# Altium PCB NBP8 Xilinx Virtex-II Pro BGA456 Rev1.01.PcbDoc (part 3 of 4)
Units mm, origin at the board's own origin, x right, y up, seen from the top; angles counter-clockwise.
Board outline 69 x 99.5 mm, 8 copper layers (Top Layer, InternalPlane1, InternalPlane2, MidLayer1, MidLayer2, MidLayer3, MidLayer4, Bottom Layer), stack 1.545 mm thick; 164 components, 314 nets, 1132 pads, 807 vias.
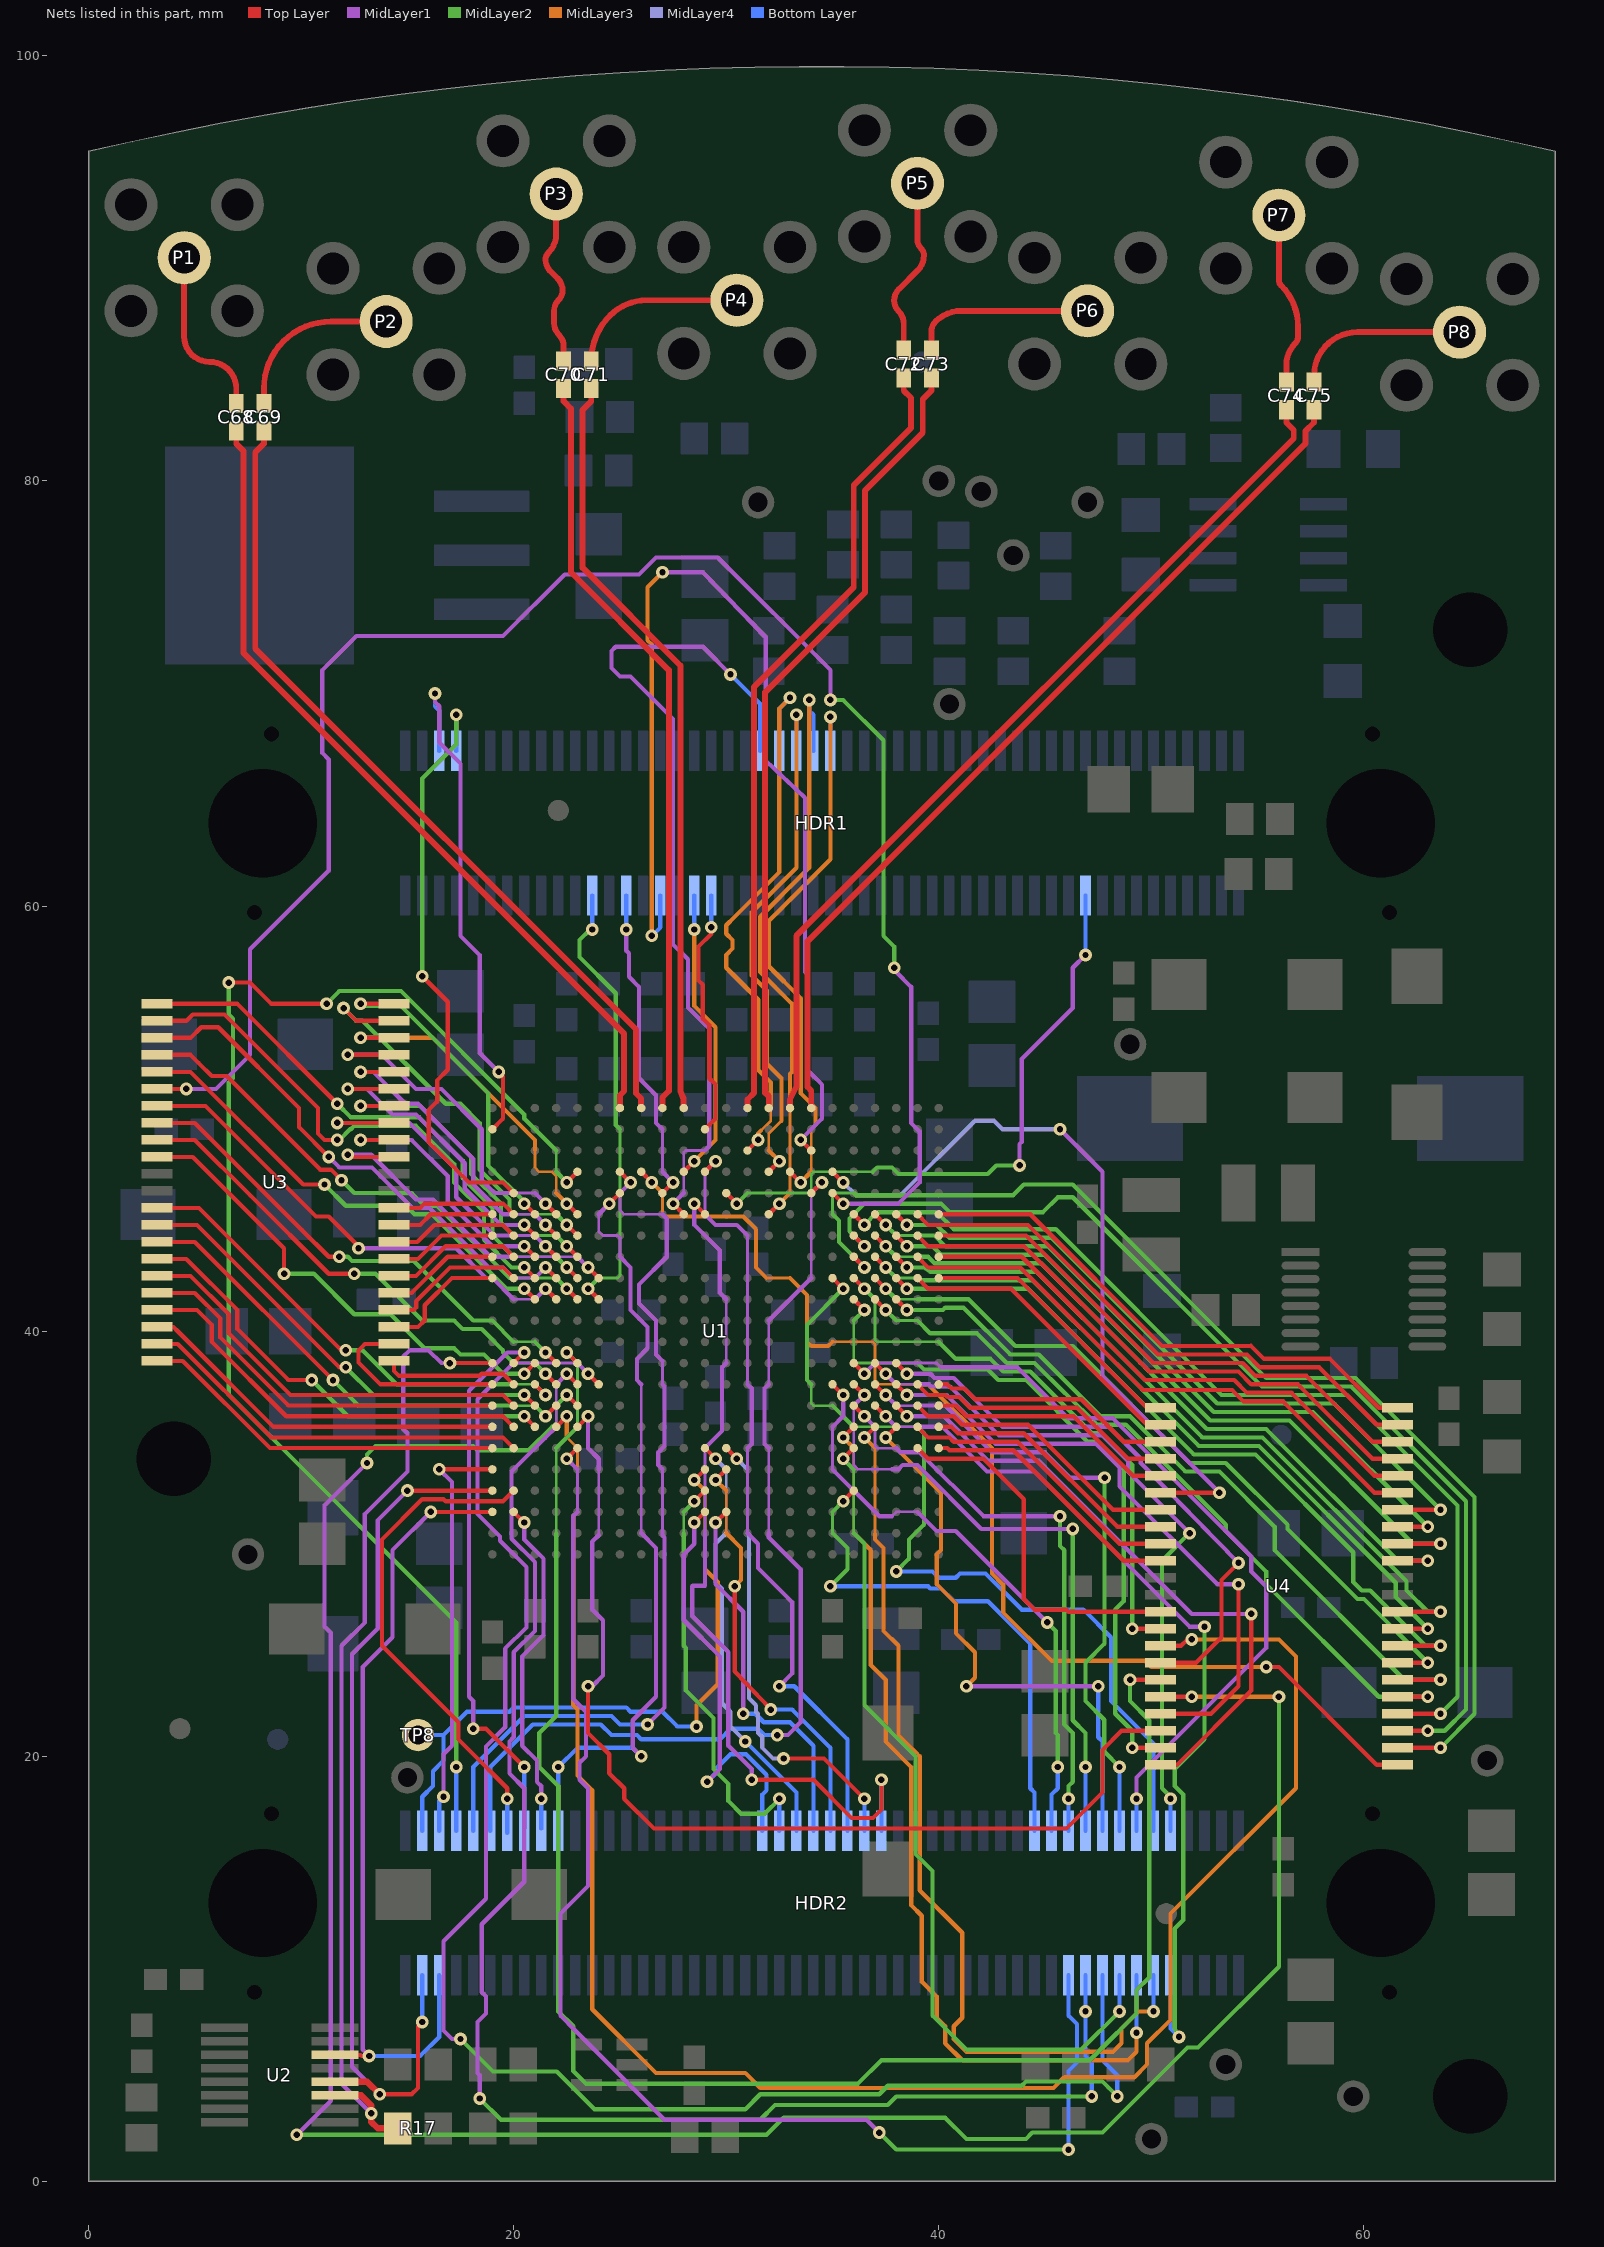
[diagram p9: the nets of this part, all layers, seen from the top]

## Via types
v1: diameter 0.6, hole 0.3, Top Layer to Bottom Layer, tented bottom, 695 vias
v2: diameter 0.9, hole 0.5, Top Layer to Bottom Layer, tented bottom, 45 vias
v3: diameter 1.8, hole 1, Top Layer to Bottom Layer, tented bottom, 26 vias
v4: diameter 1, hole 0.7, Top Layer to Bottom Layer, tented bottom, 17 vias
v5: diameter 1, hole 0.5, Top Layer to Bottom Layer, tented bottom, 15 vias
v6: diameter 1.5, hole 1, Top Layer to Bottom Layer, tented bottom, 4 vias
v7: diameter 0.8, hole 0.4, Top Layer to Bottom Layer, tented bottom, 3 vias
v8: diameter 0.9, hole 0.5, Top Layer to Bottom Layer, 2 vias

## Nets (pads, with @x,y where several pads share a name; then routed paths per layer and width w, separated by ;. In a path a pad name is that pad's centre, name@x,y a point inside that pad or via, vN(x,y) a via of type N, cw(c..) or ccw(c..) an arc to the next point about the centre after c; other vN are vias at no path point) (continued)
RAM_ADDR13: HDR1.35 U1.W13 | length 14
  Top Layer w0.2: U1.W13@28,47.5 v1(28.5,48)
  MidLayer3 w0.2: v1(28.5,48) 29.5,49 29.5,54.3 28.5,55.3 v1(28.5,58.9)
  Bottom Layer w0.2: v1(28.5,58.9) 28.5,59.1 HDR1.35@28.5,60.5
RAM_ADDR14: HDR1.31 U1.Y7 | length 51.6
  Top Layer w0.2: v1(33.5,49) U1.Y7@34,48.5
  MidLayer1 w0.2: v1(27,75.7) 28.9,75.7 31.855,72.645 31.855,66.845 33.7,65.1 33.7,56.9 33.8,56.8 33.8,52.3 34.5,51.6 34.5,50 v1(33.5,49)
  MidLayer3 w0.2: v1(26.5,58.6) 26.5,72.3 26.3,72.5 26.3,75 26.8,75.5 v1(27,75.7)
  Bottom Layer w0.2: v1(26.5,58.6) 26.9,59 HDR1.31@26.9,60.5
RAM_ADDR15: HDR1.27 U1.V14 | length 15.1
  Top Layer w0.2: U1.V14@27,46.5 v1(27.5,47)
  MidLayer1 w0.127: 27,47.5 27,49.5
  MidLayer1 w0.2: v1(25.3,58.9) 25.3,57.9 25.422,57.778 25.422,56.678 25.9,56.2 25.9,51.9 26.7,51.1 26.7,49.8 27,49.5 ; 27,47.5 v1(27.5,47)
  Bottom Layer w0.2: v1(25.3,58.9) HDR1.27@25.3,60.5
RAM_ADDR16: HDR1.23 U1.N17 | length 21.4
  Top Layer w0.2: v1(23.5,42) U1.N17@24,41.5
  MidLayer2 w0.127: 24,42.5 24.9,42.5 25,42.6 25,49.5
  MidLayer2 w0.2: v1(23.5,42) 24,42.5 ; v1(23.7,58.9) 23.6,58.9 23.1,58.4 23.1,57.6 24.8,55.9 24.8,49.7 25,49.5
  Bottom Layer w0.2: v1(23.7,58.9) HDR1.23@23.7,60.5
RAM_CS: HDR1.37 U1.AA12 | length 12
  Top Layer w0.2: U1.AA12@29,49.5 29.5,50 29.5,51.6 29.2,51.9 29.2,54.4 28.9,54.7 28.9,56.3 28.7,56.5 28.7,58.1 29.3,58.7 v1(29.3,59)
  Bottom Layer w0.2: v1@29.3,58.8 v1(29.3,59) HDR1.37@29.3,60.5
RED0: HDR1.6 U1.AA22 | length 24.8
  Top Layer w0.2: U1.AA22@19,49.5 19.5,50 19.5,52 v1(19.3,52.2)
  MidLayer1 w0.2: v1(16.3,70) 16.3,69.6 16.5,69.4 16.5,67.7 17.5,66.7 17.5,58.6 18.4,57.7 18.4,53.1 v1(19.3,52.2)
  Bottom Layer w0.2: v1(16.3,70) 16.3,69.4 16.5,69.2 HDR1.6@16.5,67.3
RED1: HDR1.8 U1.V21 | length 28.3
  Top Layer w0.2: v1(15.7,56.7) 16.9,55.5 16.9,52.3 16.4,51.8 16.4,50.8 16,50.4 16,48.9 17.9,47 19.5,47 U1.V21@20,46.5
  MidLayer2 w0.2: v1(15.7,56.7) 15.7,66 17.3,67.6 v1(17.3,69)
  Bottom Layer w0.2: HDR1.8@17.3,67.3 v1(17.3,69)
REF_CLK: HDR2.4 TP8.1 U1.E12 | length 32.1
  Top Layer w0.2: v1(28.5,33) U1.E12@29,33.5
  MidLayer3 w0.127: 29,30.5 29,32.5
  MidLayer3 w0.2: v1(28.5,33) 29,32.5 ; v1(28.6,21.4) 28.6,22.4 29.6,23.4 29.6,28.2 29,28.8 29,30.5
  Bottom Layer w0.2: TP8.1@15.5,21 16.7,21 ; HDR2.4@15.7,16.5 15.7,18.1 16.2,18.6 16.2,19.3 16.7,19.8 16.7,21 ; v1(28.6,21.4) 27.7,21.4 27,22.1 25.5,22.1 25.3,22.3 20,22.3 19.8,22.1 17.8,22.1 16.7,21
RX0N: C68.2 P1.1 | length 8.2
  Top Layer w0.279: P1.1@4.5,90.5 4.5,86.8 ccw(c5.7,86.8) 5.7,85.6 cw(c5.7,84.35) 6.95,84.35 C68.2@6.95,83.65
RX0P: C69.2 P2.1 | length 8.2
  Top Layer w0.279: C69.2@8.25,83.65 8.25,84.35 cw(c11.4,84.35) 11.4,87.5 P2.1@14,87.5
RX1N: C72.2 P5.1 | length 8.6
  Top Layer w0.279: C72.2@38.35,86.15 38.35,87.396 ccw(c37.496,87.396) 38.1,88 cw(c38.583,88.483) 37.9,88.483 cw(c38.666,88.483) 38.124,89.024 39.005,89.905 ccw(c38.293,90.617) 39.3,90.617 ccw(c38.859,90.617) 39.171,90.929 cw(c39.583,91.341) 39,91.341 P5.1@39,94
RX1P: C73.2 P6.1 | length 8.7
  Top Layer w0.279: C73.2@39.65,86.15 39.65,87.017 cw(c40.333,87.017) 39.85,87.5 cw(c41.057,86.293) 41.057,88 P6.1@47,88
SCL: HDR2.5 U1.C22 U2.14 | length 38.1
  Top Layer w0.2: U2.14@11.6,5.953 12.798,5.953 12.85,5.9 v1(13.2,5.9) ; v1(16.1,31.5) 16.9,31.5 U1.C22@19,31.5
  MidLayer1 w0.2: v1(13.2,5.9) 12.9,6.2 12.9,24.2 14.3,25.6 14.3,29.7 v1(16.1,31.5)
  Bottom Layer w0.2: v1(13.2,5.9) 15.6,5.9 16.5,6.8 HDR2.5@16.5,9.7
SDA: HDR2.3 U1.D22 U2.12 | length 43.7
  Top Layer w0.2: v1(13.7,4.1) 15.2,4.1 15.5,4.4 15.5,7.3 v1(15.7,7.5) ; v1(15,32.5) U1.D22@19,32.5
  Top Layer w0.3: U2.12@11.6,4.683 13.117,4.683 v1(13.7,4.1)
  MidLayer1 w0.2: v1(13.7,4.1) 12.4,5.4 12.4,24.8 13.6,26 13.6,31.1 v1(15,32.5)
  Bottom Layer w0.2: v1(15.7,7.5) HDR2.3@15.7,9.7
SP0: HDR2.79 U1.F18 | length 63.3
  Top Layer w0.2: v1(22.5,34) U1.F18@23,34.5
  MidLayer1 w0.127: 23,31.5 23,33.5
  MidLayer1 w0.2: v1(22.5,34) 23,33.5 ; 23,31.5 22.8,31.3 22.8,22.7 23.4,22.1 23.4,20 23.1,19.7 23.1,18.9 23.5,18.5 23.5,13.9 22.2,12.6 22.2,7.8 22.9,7.1 27.1,2.9 36.6,2.9 v1(37.2,2.3)
  MidLayer2 w0.2: v1(37.2,2.3) 38,1.5 v1(46.1,1.5)
  Bottom Layer w0.2: v1(46.1,1.5) 46.1,5.2 ; 46.1,5.2 46.5,5.6 46.5,7.4 46.1,7.8 HDR2.79@46.1,9.7
SP1: HDR2.81 U1.J18 | length 73.7
  Top Layer w0.2: v1(22.5,38) U1.J18@23,37.5
  MidLayer1 w0.127: 22,35.5 22,37.5
  MidLayer1 w0.2: v1(18.4,3.9) 18.4,5 18.3,5.1 18.3,7.5 18.7,7.9 18.7,8.7 18.5,8.9 18.5,12.1 20.5,14.1 20.5,18.5 19.8,19.2 19.8,20.7 20,20.9 20,24.9 21,25.9 21,29.134 19.9,30.234 19.9,33.4 21.493,34.993 22,35.5 ; 22,37.5 v1(22.5,38)
  MidLayer2 w0.2: v1(18.4,3.9) 19.4,2.9 31.6,2.9 32.3,3.6 37.6,3.6 38,4 v1(47.2,4)
  Bottom Layer w0.2: HDR2.81@46.9,9.7 v1(46.9,8) 46.9,5.9 47.2,5.6 v1(47.2,4)
SP2: HDR2.83 U1.J17 | length 79.1
  Top Layer w0.2: v1(23.5,38) U1.J17@24,37.5
  MidLayer1 w0.127: 20,38.5 23,38.5
  MidLayer1 w0.2: v1(17.5,6.7) 17.1,6.7 16.7,7.1 16.7,11.3 18.7,13.3 18.7,20.466 19.6,21.366 19.6,25.066 20.6,26.066 20.6,28.9 19.357,30.143 19.357,30.343 18.3,31.4 18.3,36.8 20,38.5 ; 23,38.5 v1(23.5,38)
  MidLayer2 w0.2: v1(17.5,6.7) 19.03,5.17 22.03,5.17 23.8,3.4 30.9,3.4 31.6,4.1 37.2,4.1 37.6,4.5 43.9,4.5 44.1,4.7 47.7,4.7 48,4.4 v1(48.4,4)
  Bottom Layer w0.2: HDR2.83@47.7,9.7 47.7,7 47.7,5.7 48.4,5 v1(48.4,4)
SP3: HDR2.85 U1.F5 | length 40.6
  Top Layer w0.2: v1(35.5,34) U1.F5@36,34.5
  MidLayer2 w0.127: 36,30.5 36,33.5
  MidLayer2 w0.2: v1(35.5,34) 36,33.5 ; 36,30.5 36.5,30 36.5,22.4 38.9,20 38.9,15.4 39.7,14.6 39.7,7.8 41.3,6.2 46.7,6.2 v1(48.5,8)
  Bottom Layer w0.2: v1(48.5,8) HDR2.85@48.5,9.7
SP4: HDR2.87 U1.G5 | length 44.3
  Top Layer w0.2: v1(35.5,35) U1.G5@36,35.5
  MidLayer3 w0.127: 36,30.5 36,34.5
  MidLayer3 w0.2: v1(35.5,35) 36,34.5 ; 36,30.5 36.8,29.7 36.8,24.3 37.502,23.598 37.502,20.698 38.7,19.5 38.7,13 39.2,12.5 39.2,12 39.2,9.4 39.9,8.7 39.9,7.7 40.3,7.3 40.3,6.5 41.1,5.7 48.9,5.7 49.3,6.1 v1(49.3,7)
  Bottom Layer w0.2: v1(49.3,7) HDR2.87@49.3,9.7
SP5: HDR2.89 U1.G4 | length 43.6
  Top Layer w0.2: v1(36.5,35) U1.G4@37,35.5
  MidLayer3 w0.127: 37,30.5 37,34.5
  MidLayer3 w0.2: v1(36.5,35) 37,34.5 ; 37,30.5 37,30.2 37.4,29.8 37.4,25.9 38.1,25.2 38.1,21 38.894,20.206 39.1,20 39.1,13.7 41.1,11.7 41.1,7.7 40.7,7.3 40.7,6.7 41.3,6.1 48.2,6.1 48.6,6.5 48.6,7.2 49.4,8 v1(50.1,8)
  Bottom Layer w0.2: v1(50.1,8) HDR2.89@50.1,9.7
SP6: HDR2.91 U1.H4 | length 43.1
  Top Layer w0.2: U1.H4@37,36.5 v1(37.5,36)
  MidLayer1 w0.127: 38,35.5 39,35.5
  MidLayer1 w0.2: v1(37.5,36) 38,35.5 ; 39,35.5 40.172,35.5 42.272,33.4 44.5,33.4 51.8,26.1 v1(52.5,26.1)
  MidLayer2 w0.2: v1(51.3,6.8) 51.1,7.2 51.1,11.9 51.5,12.3 51.5,18.2 51.1,18.6 51.1,19.4 52.5,20.8 v1(52.5,26.1)
  Bottom Layer w0.2: HDR2.91@50.9,9.7 50.9,7.2 v1(51.3,6.8)
SP7: HDR2.92 U1.K4 | length 33.1
  Top Layer w0.2: U1.K4@37,38.5 v1(37.5,38)
  MidLayer1 w0.127: 38,37.5 39,37.5
  MidLayer1 w0.2: v1(37.5,38) 38,37.5 ; 39,37.5 39.534,37.5 39.634,37.4 40.534,37.4 42.834,35.1 47.7,35.1 48.9,33.9 48.9,33.4 v1(51.8,30.5)
  MidLayer2 w0.2: v1(50.9,18) 50.9,18.1 50.5,18.5 50.5,29.2 v1(51.8,30.5)
  Bottom Layer w0.2: HDR2.92@50.9,16.5 v1(50.9,18)
SP8: HDR2.90 U1.P6 | length 41.3
  Top Layer w0.2: U1.P6@35,42.5 v1(35.5,42)
  MidLayer2 w0.127: 34,37.5 34,36.6 34.1,36.5 35,36.5 ; 36,35.5 39,35.5
  MidLayer2 w0.2: 34,37.5 33.8,37.7 33.8,40.3 v1(35.5,42) ; 35,36.5 36,35.5 ; v1(38,28.7) 38.6,29.3 38.6,30.2 39.3,30.9 39.3,35.2 39,35.5
  Bottom Layer w0.2: v1(38,28.7) 39.7,28.7 40,28.4 40.8,28.4 41,28.6 42.2,28.6 43.9,26.9 46.8,26.9 48.1,25.6 48.1,22.6 50.1,20.6 50.1,18.7 HDR2.90@50.1,16.5
SP9: HDR2.88 U1.K5 | length 38.6
  Top Layer w0.2: U1.K5@36,38.5 v1(36.5,38)
  MidLayer1 w0.127: 37,38.5 39.9,38.5 40.1,38.3
  MidLayer1 w0.2: v1(36.5,38) 37,38.5 ; 40.1,38.3 43.7,38.3 46.1,35.9 48.2,35.9 52.2,31.9 54.7,29.4 54.7,28.7 55.4,28 55.4,25.1 49.3,19 v1(49.3,18)
  Bottom Layer w0.2: HDR2.88@49.3,16.5 v1(49.3,18)
SP10: HDR2.86 U1.J4 | length 30.3
  Top Layer w0.2: U1.J4@37,37.5 v1(37.5,37)
  MidLayer1 w0.127: 38,36.5 39,36.5
  MidLayer1 w0.2: v1(37.5,37) 38,36.5 ; 39,36.5 40.303,36.5 42.503,34.3 45,34.3 46.2,33.1 v1(47.8,33.1)
  MidLayer2 w0.2: v1(47.8,33.1) 47.8,25.3 46.9,24.4 46.9,22.6 47.781,21.719 47.781,20.219 v1(48.5,19.5)
  Bottom Layer w0.2: HDR2.86@48.5,16.5 v1(48.5,19.5)
SP11: HDR2.84 U1.G3 | length 27.6
  Top Layer w0.2: v1(37.5,35) U1.G3@38,35.5
  MidLayer1 w0.2: v1(41.3,23.3) v1(47.5,23.3)
  MidLayer3 w0.2: v1(37.5,35) 39.4,33.1 40.1,32.4 40.1,29.7 39.9,29.5 39.9,28.1 40.1,27.9 40.814,27.186 40.814,25.786 41.7,24.9 41.7,23.7 v1(41.3,23.3)
  Bottom Layer w0.2: v1(47.5,23.3) 47.5,20.9 47.7,20.7 47.7,18 HDR2.84@47.7,16.5
SP12: HDR2.82 U1.J5 | length 30.4
  Top Layer w0.2: U1.J5@36,37.5 v1(36.5,37)
  MidLayer1 w0.127: 36,36.5 36,33.7 36.2,33.5 37.8,33.5
  MidLayer1 w0.2: 36,36.5 v1(36.5,37) ; 37.8,33.5 38.1,33.5 38.3,33.7 39,33.7 42,30.7 v1(46.3,30.7)
  MidLayer2 w0.2: v1(46.3,30.7) 46.3,21.7 46.9,21.1 v1(46.9,19.5)
  Bottom Layer w0.2: HDR2.82@46.9,16.5 v1(46.9,19.5)
SP13: HDR2.80 U1.H5 | length 27.5
  Top Layer w0.2: U1.H5@36,36.5 v1(36.5,36)
  MidLayer1 w0.127: 37,35.5 37,34.6 37.1,34.5 38,34.5
  MidLayer1 w0.2: v1(36.5,36) 37,35.5 ; 38,34.5 38.2,34.3 39.1,34.3 42.1,31.3 v1(45.7,31.3)
  MidLayer2 w0.2: v1(45.7,31.3) 45.7,29.9 45.9,29.7 45.9,21.5 46.3,21.1 46.3,18.8 46.1,18.6 v1(46.1,18)
  Bottom Layer w0.2: HDR2.80@46.1,16.5 v1(46.1,18)
SP14: HDR2.78 U1.J6 | length 27.8
  Top Layer w0.2: U1.J6@35,37.5 v1(35.5,37)
  MidLayer1 w0.127: 35,33.5 35,35.5 ; 37.8,31.3 38,31.5 39,31.5
  MidLayer1 w0.2: 35,33.5 37.2,31.3 37.8,31.3 ; 35,35.5 35.5,36 v1(35.5,37) ; 39,31.5 39.9,30.6 40.8,30.6 43.6,27.8 v1(45.1,26.3)
  MidLayer2 w0.2: v1(45.1,26.3) 45.5,25.9 45.5,21.1 45.6,21 v1(45.6,19.5)
  Bottom Layer w0.2: HDR2.78@45.3,16.5 45.3,18.2 45.6,18.5 v1(45.6,19.5)
SP15: HDR2.76 U1.D5 | length 24.9
  Top Layer w0.2: v1(35.5,32) U1.D5@36,32.5
  MidLayer2 w0.127: 35,30.5 35,31.5
  MidLayer2 w0.2: v1(34.9,28) 35.7,28.8 35.7,29.8 35,30.5 ; 35,31.5 v1(35.5,32)
  Bottom Layer w0.2: v1(34.9,28) 39.5,28 39.6,27.9 40.1,27.9 40.7,27.3 42.3,27.3 44.3,25.3 44.3,18.5 44.5,18.3 HDR2.76@44.5,16.5
SPI_CLK: HDR1.46 U1.Y10 | length 26.8
  Top Layer w0.2: U1.Y10@31,48.5 v1(31.5,49)
  MidLayer3 w0.127: 31.637,49.437 32.1,49.9 32.1,50.5
  MidLayer3 w0.2: v1(31.5,49) 31.5,49.3 31.637,49.437 ; 32.1,50.5 32.1,51.7 31.506,52.294 31.506,55.594 30,57.1 30,57.7 30.3,58 30.3,58.4 30,58.7 30,59.1 30.386,59.486 32.5,61.6 32.5,69.3 v1(33,69.8)
  Bottom Layer w0.2: HDR1.46@32.5,67.3 32.5,69.3 v1(33,69.8)
SPI_DIN: HDR1.44 U1.U13 | length 40.5
  Top Layer w0.2: v1(27.5,46) U1.U13@28,45.5
  MidLayer1 w0.127: 28,46.5 28,48.4 28.1,48.5 29,48.5
  MidLayer1 w0.2: v1(27.5,46) 28,46.5 ; 29,48.5 29.2,48.7 29.2,54.234 28.2,55.234 28.2,57.5 27.5,58.2 27.5,68.8 25.5,70.8 25,70.8 24.6,71.2 24.6,72 24.8,72.2 28.9,72.2 v1(30.2,70.9)
  Bottom Layer w0.2: v1(30.2,70.9) 30.7,70.4 31.6,69.5 HDR1.44@31.6,67.3
SPI_DOUT: HDR1.50 U1.U9 | length 28.7
  Top Layer w0.2: U1.U9@32,45.5 v1(32.5,46)
  MidLayer3 w0.127: 33,46.5 33,50.5
  MidLayer3 w0.2: v1(32.5,46) 33,46.5 ; 33,50.5 33,52.1 33.1,52.2 33.1,55.4 31.6,56.9 31.6,59.5 33.5,61.4 33.9,61.8 v1(33.9,69.7)
  Bottom Layer w0.2: v1(33.9,69.7) 33.9,69.2 34.1,69 HDR1.50@34.1,67.3
SPI_MODE: HDR1.52 U1.W8 | length 26.7
  Top Layer w0.2: U1.W8@33,47.5 v1(33.5,47)
  MidLayer3 w0.127: 34,47.5 34,49.5
  MidLayer3 w0.2: v1(33.5,47) 34,47.5 ; 34,49.5 34.2,49.7 34.2,50.5 33.5,51.2 33.5,55.669 32,57.169 32,59.3 34.9,62.2 v1(34.9,68.9)
  Bottom Layer w0.2: HDR1.52@34.9,67.3 v1(34.9,68.9) v1@34.9,69
SPI_SEL: HDR1.48 U1.W9 | length 25.3
  Top Layer w0.2: U1.W9@32,47.5 v1(32.5,48)
  MidLayer3 w0.127: 32,48.5 32,49.3 32.6,49.9
  MidLayer3 w0.2: 32,48.5 v1(32.5,48) ; 32.6,49.9 32.6,51.9 31.906,52.594 31.906,56.028 31.2,56.734 31.2,59.7 33.3,61.8 v1(33.3,69)
  Bottom Layer w0.2: HDR1.48@33.3,67.3 v1(33.3,69)
SRAM0_A0: U1.N20 U3.5 | length 22.2
  Top Layer w0.2: U3.5@3.225,52.2 4.8,52.2 10.1,46.9 v1(11.1,46.9) ; v1(20.5,42) U1.N20@21,41.5
  MidLayer2 w0.2: v1(11.1,46.9) 12.1,45.9 14.934,45.9 15.334,45.5 16.166,45.5 19.666,42 v1(20.5,42)
SRAM0_A1: U1.N18 U3.4 | length 24.5
  Top Layer w0.2: U3.4@3.225,53 4.8,53 5.2,52.6 5.799,52.001 6.499,52.001 10.9,47.6 11.4,47.6 v1(11.9,47.1) ; v1(22.5,42) U1.N18@23,41.5
  MidLayer2 w0.127: 19.8,42.5 22,42.5
  MidLayer2 w0.2: v1(11.9,47.1) 12.5,46.5 15.2,46.5 15.8,45.9 16.4,45.9 19.8,42.5 ; 22,42.5 v1(22.5,42)
SRAM0_A2: U1.P19 U3.3 | length 24.8
  Top Layer w0.2: U3.3@3.225,53.8 3.9,53.8 4.8,53.8 5.3,54.3 6.1,54.3 9.9,50.5 9.9,49.6 v1(11.3,48.2) ; v1(21.5,43) U1.P19@22,42.5
  MidLayer1 w0.127: 20,42.5 21,42.5
  MidLayer1 w0.2: v1(11.3,48.2) 11.8,47.7 13.334,47.7 15.234,45.8 16.034,45.8 18.834,43 19.5,43 20,42.5 ; 21,42.5 v1(21.5,43)
SRAM0_A3: U1.P20 U3.2 | length 25.6
  Top Layer w0.2: U3.2@3.225,54.6 4.6,54.6 4.9,54.9 6.4,54.9 10.8,50.5 10.8,49.3 11.1,49 v1(11.7,49) ; v1(20.5,43) U1.P20@21,42.5
  MidLayer2 w0.2: v1(11.7,49) 11.8,49 12.3,49.5 12.334,49.5 12.495,49.66 15.408,49.66 17.2,47.869 17.2,47 18.6,45.6 18.6,44.3 19.9,43 v1(20.5,43)
SRAM0_A4: U1.P18 U3.1 | length 26.4
  Top Layer w0.2: U3.1@3.225,55.4 7,55.4 v1(11.7,50.7) ; v1(22.5,43) U1.P18@23,42.5
  MidLayer2 w0.127: 20,43.5 22,43.5
  MidLayer2 w0.2: v1(11.7,50.7) 12.34,50.06 15.574,50.06 17.6,48.034 17.6,47.2 19,45.8 19,44.5 20,43.5 ; 22,43.5 v1(22.5,43)
SRAM0_A5: U1.U20 U3.44 | length 15.9
  Top Layer w0.2: v1(12.8,55.4) U3.44@14.375,55.4 ; v1(20.5,46) U1.U20@21,45.5
  MidLayer2 w0.2: v1(12.8,55.4) 12.9,55.3 14.7,55.3 18.8,51.2 18.8,47.8 20.5,46.1 v1(20.5,46)
SRAM0_A6: U1.T18 U3.43 | length 19.6
  Top Layer w0.2: v1(12,55.2) 12.6,54.6 U3.43@14.375,54.6 ; v1(22.5,45) U1.T18@23,44.5
  MidLayer2 w0.127: 20,45.5 22,45.5
  MidLayer2 w0.2: v1(12,55.2) 12.6,54.6 12.9,54.6 16.802,50.698 17.502,50.698 18.4,49.8 18.4,47.6 19.8,46.2 19.8,45.7 20,45.5 ; 22,45.5 v1(22.5,45)
SRAM0_A7: U1.U18 U3.42 | length 16.4
  Top Layer w0.2: v1(12.8,53.8) U3.42@14.375,53.8 ; v1(22.5,46) U1.U18@23,45.5
  MidLayer3 w0.127: 21,48.5 21,47.7 21.2,47.5 21.8,47.5 22,47.3 22,46.5
  MidLayer3 w0.2: v1(12.8,53.8) 16.2,53.8 21,49 21,48.5 ; 22,46.5 v1(22.5,46)
SRAM0_A8: U1.H22 U3.18 | length 18.5
  Top Layer w0.2: U3.18@3.225,41.8 5,41.8 6.2,40.6 6.2,39.7 9.4,36.5 U1.H22@19,36.5
SRAM0_A9: U1.R22 U3.27 | length 5.3
  Top Layer w0.2: U3.27@14.375,41.8 15.2,41.8 16.9,43.5 U1.R22@19,43.5
SRAM0_A10: U1.P21 U3.26 | length 6.8
  Top Layer w0.2: U3.26@14.375,41 15.3,41 15.413,41.113 15.413,41.413 17,43 19.5,43 U1.P21@20,42.5
SRAM0_A11: U1.P22 U3.25 | length 6
  Top Layer w0.2: U3.25@14.375,40.2 15.5,40.2 15.819,40.519 15.819,41.219 17.1,42.5 U1.P22@19,42.5
SRAM0_A12: U1.J22 U3.24 | length 9.1
  Top Layer w0.2: U3.24@14.375,39.4 13,39.4 12.7,39.1 12.7,38.531 13.731,37.5 U1.J22@19,37.5
SRAM0_A13: U1.J21 U3.23 | length 6.4
  Top Layer w0.2: U3.23@14.375,38.6 14.375,38.125 14.6,37.9 18.4,37.9 18.5,38 19.5,38 U1.J21@20,37.5
SRAM0_A14: U1.F22 U3.22 | length 17.5
  Top Layer w0.2: U3.22@3.225,38.6 4.434,38.6 8.534,34.5 U1.F22@19,34.5
SRAM0_A15: U1.F21 U3.21 | length 18.8
  Top Layer w0.2: U3.21@3.225,39.4 4.2,39.4 8.6,35 19.5,35 U1.F21@20,34.5
SRAM0_A16: U1.G22 U3.20 | length 17.7
  Top Layer w0.2: U3.20@3.225,40.2 4,40.2 4.2,40 4.6,39.6 8.7,35.5 U1.G22@19,35.5
SRAM0_A17: U1.G21 U3.19 | length 19.5
  Top Layer w0.2: U3.19@3.225,41 5.1,41 5.8,40.3 5.8,39.5 9.3,36 19.5,36 U1.G21@20,35.5
SRAM0_A18: U1.R21 U3.28 | length 6.4
  Top Layer w0.2: U3.28@14.375,42.6 15.4,42.6 16.8,44 19.5,44 U1.R21@20,43.5
SRAM0_D0: U1.N19 U3.7 | length 23.3
  Top Layer w0.2: U3.7@2.9,50.6 U3.7@3.225,50.6 5.5,50.6 10.7,45.4 11.3,45.4 12.7,44 v1(12.7,43.9) ; v1(21.5,42) U1.N19@22,41.5
  MidLayer1 w0.127: 20,41.5 21,41.5
  MidLayer1 w0.2: v1(12.7,43.9) 17.3,43.9 18.7,42.5 19,42.5 20,41.5 ; 21,41.5 v1(21.5,42)
SRAM0_D1: U1.K19 U3.8 | length 23.5
  Top Layer w0.2: U3.8@3.225,49.8 5,49.8 10.025,44.775 11.3,43.5 v1(11.8,43.5) ; v1(21.5,39) U1.K19@22,38.5
  MidLayer2 w0.127: 20,39.5 21,39.5
  MidLayer2 w0.2: v1(11.8,43.5) 12.2,43.5 12.4,43.3 15.3,43.3 18.1,40.5 19,40.5 20,39.5 ; 21,39.5 v1(21.5,39)
SRAM0_D2: U1.J19 U3.9 | length 23.6
  Top Layer w0.2: U3.9@3.225,49 5,49 7.6,46.4 11.3,42.7 v1(12.5,42.7) ; v1(21.5,38) U1.J19@22,37.5
  MidLayer2 w0.127: 20,38.5 21,38.5
  MidLayer2 w0.2: v1(12.5,42.7) 13.5,42.7 15.7,40.5 17.2,40.5 17.6,40.1 18.5,40.1 19.5,39.1 19.5,39 20,38.5 ; 21,38.5 v1(21.5,38)
SRAM0_D3: U1.K20 U3.10 | length 22.9
  Top Layer w0.2: U3.10@3.225,48.2 4.9,48.2 5.7,47.4 9.2,43.9 v1(9.2,42.7) ; v1(20.5,38) U1.K20@21,38.5
  MidLayer2 w0.2: v1(9.2,42.7) 10.6,42.7 12.5,40.8 14.2,40.8 15.8,39.2 17.2,39.2 17.5,38.9 18.6,38.9 19.5,38 v1(20.5,38)
SRAM0_D4: U1.J20 U3.13 | length 22.6
  Top Layer w0.2: U3.13@3.225,45.8 5.2,45.8 11.9,39.1 v1(12.1,39.1) ; U1.J20@21,37.5 v1(21.5,37)
  MidLayer2 w0.127: 20,37.5 21,37.5
  MidLayer2 w0.2: v1(12.1,39.1) 12.9,39.1 14.5,37.5 20,37.5 ; 21,37.5 v1(21.5,37)
SRAM0_D5: U1.H20 U3.14 | length 21.3
  Top Layer w0.2: U3.14@3.225,45 5.1,45 11.8,38.3 v1(12.1,38.3) ; v1(20.5,37) U1.H20@21,36.5
  MidLayer2 w0.2: v1(12.1,38.3) 13.4,37 v1(20.5,37)
SRAM0_D6: U1.H19 U3.15 | length 22.4
  Top Layer w0.2: U3.15@3.225,44.2 5,44.2 v1(11.5,37.7) ; v1(21.5,36) U1.H19@22,36.5
  MidLayer2 w0.127: 20,36.5 21,36.5
  MidLayer2 w0.2: v1(11.5,37.7) 12.7,36.5 20,36.5 ; 21,36.5 v1(21.5,36)
SRAM0_D7: U1.G20 U3.16 | length 21.6
  Top Layer w0.2: U3.16@3.225,43.4 4.6,43.4 7,41 7,40.1 9.4,37.7 v1(10.5,37.7) ; v1(20.5,36) U1.G20@21,35.5
  MidLayer2 w0.2: v1(10.5,37.7) 12.2,36 v1(20.5,36)
SRAM0_D8: U1.T22 U3.29 | length 5.1
  Top Layer w0.2: U3.29@14.375,43.4 15.5,43.4 16.6,44.5 U1.T22@19,44.5
SRAM0_D9: U1.T21 U3.30 | length 6.2
  Top Layer w0.2: U3.30@14.375,44.2 15.466,44.2 16.266,45 19.5,45 U1.T21@20,44.5
SRAM0_D10: U1.U22 U3.31 | length 4.8
  Top Layer w0.2: U3.31@14.375,45 15.6,45 16.1,45.5 U1.U22@19,45.5
SRAM0_D11: U1.U21 U3.32 | length 5.9
  Top Layer w0.2: U3.32@14.375,45.8 15.6,45.8 15.8,46 19.5,46 U1.U21@20,45.5
SRAM0_D12: U1.P17 U3.35 | length 16.5
  Top Layer w0.2: v1(12.2,48.3) 12.2,48.2 U3.35@14.375,48.2 ; v1(23.5,43) U1.P17@24,42.5
  MidLayer1 w0.127: 20,43.5 23,43.5
  MidLayer1 w0.2: v1(12.2,48.3) 13.3,48.3 15.4,46.2 16.2,46.2 18.9,43.5 20,43.5 ; 23,43.5 v1(23.5,43)
SRAM0_D13: U1.R20 U3.36 | length 12.8
  Top Layer w0.2: v1(12.8,49) U3.36@14.375,49 ; v1(20.5,44) U1.R20@21,43.5
  MidLayer1 w0.2: v1(12.8,49) 15.2,49 16.9,47.3 16.9,46.1 19,44 v1(20.5,44)
SRAM0_D14: U1.R19 U3.37 | length 16.3
  Top Layer w0.2: v1(11.7,49.8) 12.2,49.8 U3.37@14.375,49.8 ; v1(21.5,44) U1.R19@22,43.5
  MidLayer1 w0.127: 20,44.5 21,44.5
  MidLayer1 w0.2: v1(11.7,49.8) 15.1,49.8 17.3,47.6 17.3,46.3 19.1,44.5 20,44.5 ; 21,44.5 v1(21.5,44)
SRAM0_D15: U1.R18 U3.38 | length 15.7
  Top Layer w0.2: v1(12.8,50.6) U3.38@14.375,50.6 ; v1(22.5,44) U1.R18@23,43.5
  MidLayer2 w0.127: 20,44.5 22,44.5
  MidLayer2 w0.2: v1(12.8,50.6) 15.6,50.6 18,48.2 18,47.4 19.4,46 19.4,45.1 20,44.5 ; 22,44.5 v1(22.5,44)
SRAM0_E: U1.V6 U3.6 | length 83.8
  Top Layer w0.2: U3.6@3.225,51.4 v1(4.6,51.4) ; U1.V6@35,46.5 v1(35.5,46)
  MidLayer1 w0.2: v1(4.6,51.4) 6,51.4 7.6,53 7.6,57.966 11.3,61.666 11.3,66.9 11,67.2 11,71.1 12.6,72.7 19.5,72.7 22.4,75.6 25.9,75.6 26.7,76.4 29.6,76.4 34.9,71.1 v1(34.9,69.7) ; v1(35.5,46) 38.1,46 39.1,47 39.1,49.4 38.7,49.8 38.7,56.2 v1@38,56.9
  MidLayer2 w0.2: v1(34.9,69.7) 35.5,69.7 37.4,67.8 37.4,58.6 37.9,58.1 v1(37.9,57.1)
SRAM0_LB: U1.T20 U3.39 | length 14.5
  Top Layer w0.2: v1(12.2,51.4) U3.39@14.375,51.4 ; v1(20.5,45) U1.T20@21,44.5
  MidLayer1 w0.2: v1(12.2,51.4) 13.1,51.4 14.3,50.2 15.4,50.2 17.7,47.9 17.7,46.7 19.4,45 v1(20.5,45)
SRAM0_OE: U1.U19 U3.41 | length 16.5
  Top Layer w0.2: v1(12.2,53) U3.41@14.375,53 ; v1(21.5,46) U1.U19@22,45.5
  MidLayer1 w0.127: 20,46.5 21,46.5
  MidLayer1 w0.2: v1(12.2,53) 13.8,53 15.401,51.399 16.601,51.399 18.5,49.5 18.5,47.1 19.1,46.5 20,46.5 ; 21,46.5 v1(21.5,46)
SRAM0_UB: U1.T19 U3.40 | length 14.7
  Top Layer w0.2: v1(12.8,52.2) U3.40@14.375,52.2 ; v1(21.5,45) U1.T19@22,44.5
  MidLayer1 w0.127: 20,45.5 21,45.5
  MidLayer1 w0.2: v1(12.8,52.2) 13.4,52.2 14.9,50.7 15.5,50.7 18.1,48.1 18.1,46.9 19.5,45.5 20,45.5 ; 21,45.5 v1(21.5,45)
SRAM0_W: U1.H21 U3.17 | length 19.8
  Top Layer w0.2: U3.17@3.225,42.6 4.8,42.6 6.6,40.8 6.6,39.9 9.5,37 19.5,37 U1.H21@20,36.5
SRAM1_A0: U1.H1 U4.5 | length 11.8
  Top Layer w0.2: U1.H1@40,36.5 40.5,36.5 40.8,36.5 41.3,36 46.1,36 46.334,36 49.134,33.2 U4.5@50.425,33.2
SRAM1_A1: U1.J2 U4.4 | length 12.9
  Top Layer w0.2: U1.J2@39,37.5 39.5,37 40.3,37 40.4,36.9 40.966,36.9 41.466,36.4 46.5,36.4 48.9,34 U4.4@50.425,34
SRAM1_A2: U1.J1 U4.3 | length 11.6
  Top Layer w0.2: U1.J1@40,37.5 40.4,37.5 ; 40.3,37.5 40.4,37.5 ; U4.3@50.425,34.8 48.7,34.8 46.7,36.8 41.7,36.8 41.2,37.3 40.6,37.3 40.4,37.5
SRAM1_A3: U1.P2 U4.2 | length 14.3
  Top Layer w0.2: U1.P2@39,42.5 39.5,42 43.4,42 49.8,35.6 U4.2@50.425,35.6
SRAM1_A4: U1.P1 U4.1 | length 13
  Top Layer w0.2: U1.P1@40,42.5 43.7,42.5 49.8,36.4 U4.1@50.425,36.4
SRAM1_A5: U1.U1 U4.44 | length 25.4
  Top Layer w0.2: U1.U1@40,45.5 44.3,45.5 50.5,39.3 54.69,39.31 55.3,38.7 58.4,38.7 60.7,36.4 U4.44@61.575,36.4 U4.44@61.6,36.4
SRAM1_A6: U1.U2 U4.43 | length 26.8
  Top Layer w0.2: U1.U2@39,45.6 U1.U2@39,45.5 39.5,45 44.2,45 50.3,38.9 54.5,38.9 55.1,38.3 57.9,38.3 60.6,35.6 U4.43@61.575,35.6
SRAM1_A7: U1.T1 U4.42 | length 25.6
  Top Layer w0.2: U1.T1@40,44.5 44.1,44.5 50.1,38.5 ; 50.067,38.5 50.1,38.5 ; U4.42@61.575,34.8 60.4,34.8 57.3,37.9 54.9,37.9 54.3,38.5 50.1,38.5
SRAM1_A8: U1.H18 U4.18 | length 114.1
  Top Layer w0.2: v1(22.5,37) U1.H18@23,36.5 ; U4.18@50.425,22.8 v1(51.9,22.8)
  MidLayer1 w0.2: v1(9.8,2.2) 11.4,3.8 11.4,25.8 11.1,26.1 11.1,31.8 v1(13.1,33.8)
  MidLayer2 w0.127: 21.8,35.5 22,35.7 22,36.5
  MidLayer2 w0.2: v1(9.8,2.2) 31.9,2.2 32.7,3 40.3,3 41.3,2 44.1,2 44.4,2.3 47.7,2.3 51.7,6.3 52.2,6.3 56,10.1 v1(56,22.8) ; v1(13.1,33.8) 13.1,34.2 13.5,34.6 18.1,34.6 18.3,34.4 20.7,34.4 21.8,35.5 ; 22,36.5 v1(22.5,37)
  MidLayer3 w0.2: v1(51.9,22.8) v1(56,22.8)
SRAM1_A9: U1.N4 U4.27 | length 35.7
  Top Layer w0.2: U1.N4@37,41.5 v1(37.5,41) ; U4.27@61.6,22.8 v1(63,22.8)
  MidLayer2 w0.127: 38,40.5 39,40.5
  MidLayer2 w0.2: v1(37.5,41) 38,40.5 ; 39,40.5 39.6,39.9 41.8,39.9 43.2,38.5 44.5,38.5 47.434,35.6 48.8,35.6 51.2,33.2 53.5,30.9 53.5,30.6 55.4,28.7 55.4,28.1 60.7,22.8 v1(63,22.8)
SRAM1_A10: U1.U5 U4.26 | length 46.7
  Top Layer w0.2: U1.U5@36,45.5 v1(36.5,45) ; U4.26@61.6,22 v1(63.6,22)
  MidLayer2 w0.2: v1(36.5,45) 37.1,45.6 39.9,45.6 40.7,44.8 45.5,44.8 53.3,37 59.2,37 64.4,31.8 64.4,22.8 v1(63.6,22)
SRAM1_A11: U1.T5 U4.25 | length 51.4
  Top Layer w0.2: U1.T5@36,44.5 v1(36.5,44) ; U4.25@61.6,21.2 v1(63,21.2)
  MidLayer2 w0.2: v1(36.5,44) 35.8,44.7 35.8,45.3 36.5,46 40.1,46 40.5,45.6 44.9,45.6 45.6,46.3 46.3,46.3 55.2,37.4 59.4,37.4 64.8,32 64.8,22.2 63.8,21.2 v1(63,21.2)
SRAM1_A12: U1.R5 U4.24 | length 55.8
  Top Layer w0.2: U1.R5@36,43.5 v1(36.5,43) ; U4.24@61.6,20.4 v1(63.6,20.4)
  MidLayer2 w0.127: 35,45.5 35,46.4 35.1,46.5 36,46.5
  MidLayer2 w0.2: 35,45.5 35.3,45.2 35.3,44.2 v1(36.5,43) ; 36,46.5 36.1,46.4 43.5,46.4 44,46.9 46.3,46.9 55.4,37.8 59.6,37.8 65.2,32.2 65.2,22 v1(63.6,20.4)
SRAM1_A13: U1.W15 U4.23 | length 55.4
  Top Layer w0.2: U1.W15@26,47.5 v1(26.5,47) ; v1(55.4,24.2) 56,24.2 60.6,19.6 U4.23@61.575,19.6
  MidLayer3 w0.127: 27,45.5 27,46.5 ; 31.9,42.5 33,42.5 ; 35,39.5 36.9,39.5 37,39.4 37,37.7 37.2,37.5 39,37.5
  MidLayer3 w0.2: v1(26.5,47) 27,46.5 ; 27,45.5 27.1,45.4 30.8,45.4 31.4,44.8 31.4,43 31.9,42.5 ; 33,42.5 33.8,41.7 33.8,39.5 34,39.3 34.8,39.3 35,39.5 ; 39,37.5 39.5,37.5 42.5,34.5 42.5,28.6 43.028,28.072 43.028,26.772 45.3,24.5 49.7,24.5 50,24.2 v1(55.4,24.2)
SRAM1_A14: U1.H3 U4.22 | length 30.1
  Top Layer w0.2: U1.H3@38,36.5 v1(38.5,36) ; U4.22@50.4,19.6 U4.22@50.425,19.6 51.2,19.6 54.7,23.1 v1(54.7,26.7)
  MidLayer1 w0.2: v1(38.5,36) 40.237,36 42.337,33.9 44.7,33.9 51.9,26.7 v1(54.7,26.7)
SRAM1_A15: U1.N5 U4.21 | length 33.1
  Top Layer w0.2: U1.N5@36,41.5 v1(36.5,41) ; v1(49.1,20.4) U4.21@50.425,20.4 U4.21@50.5,20.4
  MidLayer2 w0.127: 36,40.5 36,38.6 36.1,38.5 39,38.5
  MidLayer2 w0.2: 36,40.5 v1(36.5,41) ; 39,38.5 39.3,38.2 42.3,38.2 42.8,37.7 44.1,37.7 47,34.8 47.4,34.8 48.7,33.5 48.7,27.3 48.3,26.9 48.3,22 49.1,21.2 v1(49.1,20.4)
SRAM1_A16: U1.G18 U4.20 | length 49.4
  Top Layer w0.2: U1.G18@23,35.5 v1(23.5,36) ; v1(23.5,23.3) 23.5,21.1 24.5,20.1 24.5,19.2 25.2,18.5 25.2,18 26.6,16.6 46,16.6 47.7,18.3 47.7,20.3 48.6,21.2 U4.20@50.425,21.2
  MidLayer1 w0.127: 24,30.4 24,33.5
  MidLayer1 w0.2: v1(23.5,23.3) v1@23.7,23.3 ; v1(23.5,36) 23.5,34.5 24,34 24,33.5 ; v1@23.6,23.2 v1@23.7,23.3 ; 24,30.4 23.7,30.1 23.7,26.9 24.2,26.4 24.2,23.8 v1@23.7,23.3
SRAM1_A17: U1.J3 U4.19 | length 29.6
  Top Layer w0.2: U1.J3@38,37.5 v1(38.5,37) ; U4.19@50.4,22 U4.19@50.425,22 52.8,22 54.1,23.3 v1(54.1,28.1)
  MidLayer1 w0.2: v1(38.5,37) 40.369,37 42.669,34.7 47.4,34.7 48.5,33.6 48.5,32.7 53.1,28.1 v1(54.1,28.1)
SRAM1_A18: U1.N3 U4.28 | length 35.7
  Top Layer w0.2: U1.N3@38,41.5 v1(38.5,41) ; U4.28@61.6,23.6 v1(63.6,23.6)
  MidLayer2 w0.2: v1(38.5,41) 40.2,41 40.3,41.1 41.166,41.1 43.366,38.9 44.7,38.9 47.6,36 49,36 51.6,33.4 53.2,33.4 55.8,30.8 55.8,29.7 61.9,23.6 v1(63.6,23.6)
SRAM1_D0: U1.H2 U4.7 | length 13.5
  Top Layer w0.2: U1.H2@39,36.5 39.5,36 40.7,36 41.1,35.6 44.2,35.6 48.2,31.6 U4.7@50.425,31.6
SRAM1_D1: U1.G1 U4.8 | length 12.4
  Top Layer w0.2: U1.G1@40,35.5 40.4,35.5 40.6,35.5 40.9,35.2 44,35.2 48.4,30.8 U4.8@50.425,30.8
SRAM1_D2: U1.G2 U4.9 | length 13.7
  Top Layer w0.2: U1.G2@39,35.5 39.5,35 40.5,35 40.7,34.8 43.7,34.8 48.5,30 U4.9@50.425,30
SRAM1_D3: U1.F1 U4.10 | length 12.6
  Top Layer w0.2: U1.F1@40,34.5 40.4,34.5 40.5,34.4 43.5,34.4 48.7,29.2 U4.10@50.425,29.2
SRAM1_D4: U1.F2 U4.13 | length 17.4
  Top Layer w0.2: U1.F2@39,34.5 39.5,34 42.1,34 44,32.1 44,27.4 44.5,26.9 46,26.9 46.1,26.8 U4.13@50.425,26.8
SRAM1_D5: U1.P5 U4.14 | length 26.9
  Top Layer w0.2: U1.P5@36,42.5 v1(36.5,42) ; v1(49.1,26) U4.14@50.4,26
  MidLayer2 w0.127: 37,41.5 37,39.6 37.1,39.5 40,39.5
  MidLayer2 w0.2: v1(36.5,42) 37,41.5 ; 40,39.5 40.8,38.7 42.434,38.7 43.034,38.1 44.3,38.1 47.2,35.2 47.6,35.2 49.1,33.7 v1(49.1,26)
SRAM1_D6: U1.G19 U4.15 | length 86.3
  Top Layer w0.2: U1.G19@22,35.5 v1(22.5,36) ; U4.15@50.425,25.2 51.4,25.2 51.7,25.5 v1(51.9,25.5)
  MidLayer3 w0.127: 22.5,35 23,34.5 23,31.5
  MidLayer3 w0.2: 22.5,35 v1(22.5,36) ; 23,31.5 22.8,31.3 22.8,22.4 23,22.2 23,19.1 23.285,18.815 23.7,18.4 23.7,8.1 26.7,5.1 30.9,5.1 31.6,4.4 45.4,4.4 45.9,4.9 49.2,4.9 49.8,5.5 49.8,6.5 50.9,7.6 50.9,12.6 56.8,18.5 56.8,24.7 56,25.5 v1(51.9,25.5)
SRAM1_D7: U1.K3 U4.16 | length 27.4
  Top Layer w0.2: U1.K3@38,38.5 v1(38.5,38) ; U4.16@50.4,24.4 U4.16@50.425,24.4 52.1,24.4 53.3,25.6 53.3,28.3 v1(54.1,29.1)
  MidLayer1 w0.2: v1(38.5,38) 39.6,38 39.8,37.8 40.7,37.8 43,35.5 48,35.5 49.5,34 49.5,33.8 v1(54.1,29.1)
SRAM1_D8: U1.P4 U4.29 | length 35
  Top Layer w0.2: U1.P4@37,42.5 v1(37.5,42) ; U4.29@61.6,24.4 v1(63,24.4)
  MidLayer2 w0.127: 38,41.5 39,41.5
  MidLayer2 w0.2: v1(37.5,42) 38,41.5 ; 39,41.5 41.4,41.5 43.433,39.467 43.6,39.3 46.3,39.3 51.8,33.8 53.5,33.8 56.4,30.9 56.4,30.7 59.7,27.4 60,27.4 v1(63,24.4)
SRAM1_D9: U1.P3 U4.30 | length 35.6
  Top Layer w0.2: U1.P3@38,42.5 v1(38.5,42) ; U4.30@61.6,25.2 v1(63.6,25.2)
  MidLayer2 w0.2: v1(38.5,42) 44.2,42 52,34.2 54.903,34.2 59.5,29.603 59.5,28.2 59.9,27.8 60.3,27.8 62.9,25.2 v1(63.6,25.2)
SRAM1_D10: U1.R4 U4.31 | length 35
  Top Layer w0.2: U1.R4@37,43.5 v1(37.5,43) ; U4.31@61.6,26 v1(63,26)
  MidLayer2 w0.127: 38,42.5 39,42.5
  MidLayer2 w0.2: v1(37.5,43) 38,42.5 ; 39,42.5 39.1,42.4 44.4,42.4 52.234,34.6 55.069,34.6 61.5,28.169 61.5,27.5 v1(63,26)
SRAM1_D11: U1.R3 U4.32 | length 34.7
  Top Layer w0.2: U1.R3@38,43.5 v1(38.5,43) ; U4.32@61.6,26.8 v1(63.6,26.8)
  MidLayer2 w0.2: v1(38.5,43) 39.3,43 39.6,42.8 44.6,42.8 52.4,35 55.234,35 62,28.234 62,27.8 63,26.8 v1(63.6,26.8)
SRAM1_D12: U1.T4 U4.35 | length 33.7
  Top Layer w0.2: U1.T4@37,44.5 v1(37.5,44) ; U4.35@61.6,29.2 v1(63,29.2)
  MidLayer2 w0.127: 38,43.5 39,43.5
  MidLayer2 w0.2: v1(37.5,44) 38,43.5 ; 39,43.5 39.5,43.5 39.8,43.2 44.8,43.2 52.603,35.4 55.4,35.4 61.6,29.2 v1(63,29.2)
SRAM1_D13: U1.T3 U4.36 | length 33.6
  Top Layer w0.2: U1.T3@38,44.5 v1(38.5,44) ; U4.36@61.6,30 v1(63.6,30)
  MidLayer2 w0.2: v1(38.5,44) 39.3,44 39.7,44 40.1,43.6 44.969,43.6 52.769,35.8 56.5,35.8 62.3,30 v1(63.6,30)
SRAM1_D14: U1.U4 U4.37 | length 33.5
  Top Layer w0.2: U1.U4@37,45.5 v1(37.5,45) ; U4.37@61.6,30.8 v1(63,30.8)
  MidLayer2 w0.127: 38,44.5 39,44.5
  MidLayer2 w0.2: v1(37.5,45) 38,44.5 ; 39,44.5 39.8,44.5 40.3,44 45.134,44 52.934,36.2 57.6,36.2 v1(63,30.8)
SRAM1_D15: U1.U3 U4.38 | length 33.5
  Top Layer w0.2: U1.U3@38,45.5 v1(38.5,45) ; U4.38@61.5,31.6 U4.38@61.575,31.6 v1(63.6,31.6)
  MidLayer2 w0.2: v1(38.5,45) 39.9,45 40.5,44.4 45.3,44.4 53.1,36.6 58.6,36.6 v1(63.6,31.6)
SRAM1_E: U1.W6 U4.6 | length 35.8
  Top Layer w0.2: U1.W6@35,47.5 v1(35.5,47) ; U4.6@50.425,32.4 v1(53.2,32.4)
  MidLayer1 w0.2: v1(45.7,49.5) 47.7,47.5 47.7,37.9 v1(53.2,32.4)
  MidLayer4 w0.2: v1(35.5,47) 36.1,46.4 38.2,46.4 41.7,49.9 42.6,49.9 43,49.5 v1(45.7,49.5)
SRAM1_LB: U1.R2 U4.39 | length 27.2
  Top Layer w0.2: U1.R2@39,43.5 39.5,43 43.834,43 49.6,37.234 53.8,37.234 54.334,36.7 56.2,36.7 60.5,32.4 U4.39@61.575,32.4
SRAM1_OE: U1.T2 U4.41 | length 27.1
  Top Layer w0.2: U1.T2@39,44.5 39.5,44 44.003,44 49.481,38.522 49.9,38.1 54.1,38.1 54.7,37.5 56.9,37.5 60.4,34 U4.41@61.575,34 U4.41@61.7,34
SRAM1_UB: U1.R1 U4.40 | length 25.8
  Top Layer w0.2: U1.R1@40,43.5 43.9,43.5 49.7,37.7 53.9,37.7 54.5,37.1 56.6,37.1 60.5,33.2 U4.40@61.575,33.2
SRAM1_W: U1.K18 U4.17 | length 82
  Top Layer w0.2: v1(22.5,39) U1.K18@23,38.5 ; v1(49,23.6) U4.17@50.425,23.6
  MidLayer2 w0.127: 22,30.5 22,34.5 ; 23,35.5 23,38.5
  MidLayer2 w0.2: 22,30.5 22,21.9 21.2,21.1 21.2,19.5 22.1,18.6 22.1,8 22.8,7.3 22.8,5.2 23.4,4.6 36.203,4.6 36.203,4.603 37.3,5.7 47.1,5.7 47.546,6.146 49.3,7.9 49.3,9 49.9,9.6 49.9,21.7 49,22.6 v1(49,23.6) ; 22,34.5 23,35.5 ; v1(22.5,39) 23,38.5
SW0: HDR2.44 U1.C12 | length 20.6
  Top Layer w0.2: v1(28.5,31) U1.C12@29,31.5
  MidLayer1 w0.2: v1(28.5,31) 28.5,30 28,29.5 28,26.4 29.7,24.7 29.7,19.4 v1(29.1,18.8)
  Bottom Layer w0.2: v1(29.1,18.8) 29.6,19.3 29.6,19.5 30.2,20.1 30.934,20.1 31.9,19.134 31.9,18.4 31.7,18.2 HDR2.44@31.7,16.5
SW1: HDR2.46 U1.D12 | length 20.3
  Top Layer w0.2: v1(28.5,32) U1.D12@29,32.5
  MidLayer2 w0.127: 28,30.5 28,31.5
  MidLayer2 w0.2: 28,30.5 28,25.2 28.1,25.1 28.1,23.1 29.4,21.8 29.4,19.4 30.1,18.7 30.1,17.9 30.7,17.3 31.8,17.3 v1(32.5,18) ; 28,31.5 v1(28.5,32)
  Bottom Layer w0.2: HDR2.46@32.5,16.5 v1(32.5,18)
SW2: HDR2.48 U1.F12 | length 20.2
  Top Layer w0.2: U1.F12@29,34.5 v1(29.5,34)
  MidLayer4 w0.127: 30,30.5 30,33.5
  MidLayer4 w0.2: v1(29.5,34) 30,33.5 ; 30,30.5 29.5,30 29.5,28.2 29.8,27.9 29.8,22.5 30.2,22.1 30.2,21.4 v1(30.9,20.7)
  Bottom Layer w0.2: v1(30.9,20.7) 33.3,18.3 HDR2.48@33.3,16.5
SW3: HDR2.50 U1.C11 | length 18.2
  Top Layer w0.2: v1(29.5,31) U1.C11@30,31.5
  MidLayer1 w0.2: v1(29.5,31) 29.5,28.1 30.8,26.8 v1(30.8,22)
  Bottom Layer w0.2: v1(30.8,22) 31.366,22 31.766,21.6 33,21.6 34.1,20.5 34.1,18 HDR2.50@34.1,16.5
SW4: HDR2.52 U1.E11 | length 20.2
  Top Layer w0.2: v1(29.5,33) U1.E11@30,33.5 ; v1(30.4,28) 30.4,24 v1(32.1,22.2)
  MidLayer3 w0.127: 30,30.5 30,32.5
  MidLayer3 w0.2: v1(29.5,33) 30,32.5 ; 30,30.5 30.7,29.8 30.7,28.3 v1(30.4,28)
  Bottom Layer w0.2: v1(32.1,22.2) 33.1,22.2 34.9,20.4 34.9,18 HDR2.52@34.9,16.5
SW5: HDR2.54 U1.W12 | length 36.8
  Top Layer w0.2: U1.W12@29,47.5 v1(29.5,48)
  MidLayer1 w0.127: 29,45.5 29,47.5 ; 31,30.5 31,34.5 ; 31,37.5 31,44.5
  MidLayer1 w0.2: 29,45.5 29.5,45 30.5,45 31,44.5 ; 29,47.5 v1(29.5,48) ; 31,30.5 31.5,30 31.5,28.866 33.1,27.266 33.1,23.9 v1(32.5,23.3) ; 31,34.5 31.2,34.7 31.2,37.3 31,37.5
  Bottom Layer w0.2: v1(32.5,23.3) 33.2,23.3 35.7,20.8 35.7,19.5 HDR2.54@35.7,16.5
SW6: HDR2.56 U1.F11 | length 22.1
  Top Layer w0.2: U1.F11@30,34.5 v1(30.5,34) ; v1(32.7,19.9) 34.6,19.9 v1(36.5,18)
  MidLayer4 w0.127: 31,30.5 31,33.5
  MidLayer4 w0.2: v1(30.5,34) 31,33.5 ; 31,30.5 31.067,30.433 31.067,22.733 31.4,22.4 31.4,22.1 31.5,22 31.5,21.1 31.7,20.9 31.7,20.4 32.2,19.9 v1(32.7,19.9)
  Bottom Layer w0.2: HDR2.56@36.5,16.5 v1(36.5,18)
SW7: HDR2.58 U1.U12 | length 41.4
  Top Layer w0.2: v1(28.5,46) U1.U12@29,45.5 ; v1(31.2,18.9) 34.1,18.9 35.9,17.1 36.9,17.1 37.3,17.5 v1(37.3,18.9)
  MidLayer1 w0.127: 29,30.5 29,34.5 ; 30,38.5 30,41.5
  MidLayer1 w0.2: v1(28.5,46) 28.5,45 29.7,43.8 29.7,41.8 30,41.5 ; 29,30.5 29,28.027 28.427,28.027 28.4,28 28.4,26.6 30.1,24.9 30.1,20.5 31.2,19.4 v1(31.2,18.9) ; 29,34.5 29.8,35.3 29.8,38.3 30,38.5
  Bottom Layer w0.2: HDR2.58@37.3,16.5 v1(37.3,18.9)
SWC0: HDR2.18 U1.C21 | length 16.3
  Top Layer w0.2: U1.C21@20,31.5 v1(20.5,31)
  MidLayer1 w0.2: v1(20.5,31) 20.5,30.2 21.4,29.3 21.4,25.7 20.4,24.7 20.4,20.5 21.1,19.8 21.1,18.8 21.3,18.6 v1(21.3,18)
  Bottom Layer w0.2: HDR2.18@21.3,16.6 v1(21.3,18)
SWC1: HDR2.16 U1.K21 | length 26.1
  Top Layer w0.2: v1(18.1,21.3) 18.7,21.3 v1(20.5,19.5) ; U1.K21@20,38.5 v1(20.5,39)
  MidLayer1 w0.2: v1(18.1,21.3) 18.1,22.6 17.9,22.8 17.9,37.2 19.7,39 v1(20.5,39)
  Bottom Layer w0.2: HDR2.16@20.5,16.6 v1(20.5,19.5)
SWC2: HDR2.14 U1.D21 | length 23.5
  Top Layer w0.2: v1(19.7,18) 19.7,18.5 17.9,20.3 17.4,20.8 17.4,21.6 13.8,25.2 13.8,30.2 15.7,32.1 16.7,32.1 16.8,32 19.5,32 U1.D21@20,32.5
  Bottom Layer w0.2: HDR2.14@19.7,16.4 HDR2.14@19.7,16.5 v1(19.7,18)
SWC3: HDR2.6 U1.E22 | length 20
  Top Layer w0.2: v1(16.5,33.5) U1.E22@19,33.5
  MidLayer1 w0.2: v1(16.5,33.5) 17.1,32.9 17.1,20.5 16.7,20.1 v1(16.7,18.1)
  Bottom Layer w0.2: HDR2.6@16.5,16.5 16.5,17.9 v1(16.7,18.1)
SWR0: HDR2.20 U1.V16 | length 36.8
  Top Layer w0.2: v1(24.5,46) U1.V16@25,46.5
  MidLayer1 w0.127: 24,45.5 24,44.7 24.2,44.5 24.9,44.5 25,44.4 25,43.5 ; 26,30.5 26,37.5
  MidLayer1 w0.2: 24,45.5 v1(24.5,46) ; 25,43.5 25.5,43 25.5,41 26.3,40.2 26.3,39.2 25.8,38.7 25.8,37.7 26,37.5 ; v1(26,20) 25.6,20.4 25.6,21.7 26.7,22.8 26.7,29.8 26,30.5
  Bottom Layer w0.2: HDR2.20@22.1,16.6 v1(22.1,19.5) 23,20.4 25.6,20.4 v1(26,20)
SWR1: HDR2.12 U1.V7 | length 47.2
  Top Layer w0.2: U1.V7@34,46.5 v1(34.5,47)
  MidLayer1 w0.127: 32,30.5 32,34.5 ; 32,37.5 32,40.5 ; 34,42.5 34,46.5
  MidLayer1 w0.2: 32,30.5 32,30.3 33.5,28.8 33.5,21.6 32.9,21 v1(32.4,21) ; 32,34.5 31.8,34.7 31.8,37.3 32,37.5 ; 32,40.5 34,42.5 ; 34,46.5 v1(34.5,47)
  Bottom Layer w0.2: HDR2.12@18.9,16.5 18.9,19.5 20.9,21.5 24.1,21.5 24.6,21 25.8,21 26,20.8 29.7,20.8 30.2,21.3 31.5,21.3 31.8,21 v1(32.4,21)
SWR2: HDR2.10 U1.W16 | length 42.4
  Top Layer w0.2: U1.W16@25,47.5 v1(25.5,47)
  MidLayer1 w0.127: 25,46.5 25,45.7 25.2,45.5 27,45.5 ; 27,30.6 27,33.5 ; 27,37.5 27,38.6
  MidLayer1 w0.2: 25,46.5 v1(25.5,47) ; v1(26.3,21.5) 27.1,22.3 27.1,30.3 27,30.4 27,30.6 ; 27,33.5 26.8,33.7 26.8,34.3 27.1,34.6 27.1,37.4 27,37.5 ; 27,38.6 26.7,38.9 26.7,40.5 25.9,41.3 25.9,42.2 27.2,43.5 27.2,45.3 27,45.5
  Bottom Layer w0.2: HDR2.10@18.1,16.5 18.1,18 18.1,19.5 20.5,21.9 24.6,21.9 25,21.5 v1(26.3,21.5)
SWR3: HDR2.8 U1.W18 | length 66.2
  Top Layer w0.2: v1(6.6,56.4) 7.6,56.4 8.6,55.4 v1(11.2,55.4) ; v1(22.5,47) U1.W18@23,47.5
  MidLayer2 w0.127: 22,47.5 22,48.5
  MidLayer2 w0.2: v1(6.6,56.4) 6.6,54.9 6.8,54.7 6.8,51.9 6.6,51.7 6.6,37 17.3,26.3 v1(17.3,19.5) ; v1(11.2,55.4) 11.8,56 14.7,56 20.5,50.2 20.5,50 22,48.5 ; 22,47.5 v1(22.5,47)
  Bottom Layer w0.2: HDR2.8@17.3,16.5 v1(17.3,19.5)
TEMP_ALERT: R17.2 U1.K22 U2.11 | length 46.2
  Top Layer w0.2: v1(17,38.5) U1.K22@19,38.5
  Top Layer w0.3: U2.11@11.6,4.048 12.828,4.048 13.3,3.575 v1(13.3,3.2) 13.3,2.8 13.6,2.5 R17.2@14.55,2.5
  MidLayer1 w0.2: v1(13.3,3.2) 11.9,4.6 11.9,25.2 13,26.3 13,31.4 15,33.4 15,35.2 14.8,35.4 14.8,38.8 15.1,39.1 16,39.1 16.6,38.5 v1(17,38.5)
TEST: HDR1.81 U1.V11 | length 29.5
  Top Layer w0.2: U1.V11@30,46.5 v1(30.5,46)
  MidLayer1 w0.2: v1(43.8,47.8) 43.8,48.8 43.9,48.9 43.9,52.8 46.3,55.2 46.3,57.1 v1(46.9,57.7)
  MidLayer2 w0.127: 31,46.5 33.9,46.5 34,46.6 34,47.4 34.1,47.5 36.9,47.5 36.906,47.506
  MidLayer2 w0.2: v1(30.5,46) 31,46.5 ; 36.906,47.506 37.1,47.7 37.8,47.7 38.1,47.4 42.3,47.4 42.7,47.8 v1(43.8,47.8)
  Bottom Layer w0.2: v1(46.9,57.7) HDR1.81@46.9,60.5
TX0N: C71.2 P4.1 | length 8.5
  Top Layer w0.279: C71.2@23.65,85.65 cw(c26.668,85.65) 24.534,87.784 cw(c26.263,86.055) 26.263,88.5 P4.1@30.5,88.5
TX0P: C70.2 P3.1 | length 8.5
  Top Layer w0.279: P3.1@22,93.5 22,91.607 cw(c20.776,91.607) 21.641,90.741 ccw(c21.983,90.4) 21.5,90.4 ccw(c22.224,90.4) 21.712,89.888 22.064,89.536 cw(c21.493,88.966) 22.3,88.966 cw(c21.659,88.966) 22.112,88.512 ccw(c22.624,88) 21.9,88 21.9,87.436 ccw(c22.712,87.436) 22.138,86.862 cw(c21.626,86.35) 22.35,86.35 C70.2@22.35,85.65
TX1N: C75.2 P8.1 | length 8.3
  Top Layer w0.279: C75.2@57.65,84.65 57.65,84.951 cw(c59.699,84.951) 59.699,87 P8.1@64.5,87
TX1P: C74.2 P7.1 | length 8.2
  Top Layer w0.279: P7.1@56,92.5 56,89.441 ccw(c56.341,89.441) 56.1,89.2 cw(c54.169,87.269) 56.9,87.269 56.9,86.8 cw(c56.417,86.8) 56.759,86.459 ccw(c57.745,85.472) 56.35,85.472 C74.2@56.35,84.65
V_RX0N: C68.1 U1.AB16 | length 39.5
  Top Layer w0.279: C68.1@6.95,82.35 6.95,81.75 7.3,81.4 7.3,71.9 25.2,54 25.2,51.3 25,51.1 U1.AB16@25,50.5
V_RX0P: C69.1 U1.AB15 | length 39.5
  Top Layer w0.279: C69.1@8.25,82.35 8.25,81.75 7.844,81.344 7.844,72.111 25.756,54.199 25.756,51.194 26,50.95 U1.AB15@26,50.5
V_RX1N: C72.1 U1.AB10 | length 37.7
  Top Layer w0.279: U1.AB10@31,50.5 31,50.9 31.3,51.2 31.3,70.3 36,75 36,79.8 38.7,82.5 38.7,83.9 38.35,84.25 C72.1@38.35,84.85
V_RX1P: C73.1 U1.AB9 | length 37.7
  Top Layer w0.279: U1.AB9@32,50.5 32,51.047 31.833,51.214 31.833,70.06 36.533,74.76 36.533,79.561 39.244,82.271 39.244,83.844 39.65,84.25 C73.1@39.65,84.85
V_TX0N: C71.1 U1.AB13 | length 36
  Top Layer w0.279: C71.1@23.65,84.35 23.65,83.75 23.244,83.344 23.244,75.911 27.838,71.316 27.838,51.308 27.991,50.927 27.991,50.5 U1.AB13@27.991,50.495
V_TX0P: C70.1 U1.AB14 | length 36
  Top Layer w0.279: C70.1@22.35,84.35 22.35,83.75 22.7,83.4 22.7,75.7 27.3,71.1 27.3,51.3 27,51 U1.AB14@27,50.5
V_TX1N: C75.1 U1.AB7 | length 42.8
  Top Layer w0.279: U1.AB7@34,50.5 34,51.32 33.833,51.486 33.833,58.344 57.244,81.755 57.244,82.344 57.65,82.75 C75.1@57.65,83.35
V_TX1P: C74.1 U1.AB8 | length 42.8
  Top Layer w0.279: U1.AB8@33,50.5 33,50.9 33.3,51.5 33.3,58.6 56.7,82 56.7,82.4 56.35,82.75 C74.1@56.35,83.35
